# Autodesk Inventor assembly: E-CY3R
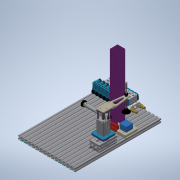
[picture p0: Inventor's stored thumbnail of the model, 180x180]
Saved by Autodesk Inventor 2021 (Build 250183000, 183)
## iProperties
Created: 2021-01
Part Number: E-CY3R
Material: Genérico
Document SubType Name: Assembly
Designer: ATOUZA
Author: ATOUZA
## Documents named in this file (20)
- D:\01 Paralaia\Grupos de Traballo\GT Maquetas\CAD 3D\E_AlimentaciónV1\EAV1.iam
- D:\01 Paralaia\Grupos de Traballo\GT Maquetas\CAD 3D\E_AlimentaciónV1\SMC_JP_MSQXB10AM9B0\MSQXB10A-M9B(0).iam
- D:\01 Paralaia\Grupos de Traballo\GT Maquetas\CAD 3D\E_AlimentaciónV1\SMC_JP_CDQMB2530M9B000\CDQMB25-30-M9B(0_0_0).iam
- D:\01 Paralaia\Grupos de Traballo\GT Maquetas\CAD 3D\E_AlimentaciónV1\Placa cilindro rotatorio.ipt
- D:\01 Paralaia\Grupos de Traballo\GT Maquetas\CAD 3D\E_AlimentaciónV1\Placa cilindro elevador.ipt
- D:\01 Paralaia\Grupos de Traballo\GT Maquetas\CAD 3D\E_AlimentaciónV1\SMC_JP_CD85N1650MBM9B000\CD85N16-50M-B-M9B(0__0_0).iam
- D:\01 Paralaia\Grupos de Traballo\GT Maquetas\CAD 3D\E_AlimentaciónV1\Cubo.ipt
- D:\01 Paralaia\Grupos de Traballo\GT Maquetas\CAD 3D\E_AlimentaciónV1\ZPT32SCK30\ZPT32CSK30-04-A10_(S) Silicon rubber.iam
- D:\01 Paralaia\Grupos de Traballo\GT Maquetas\CAD 3D\E_AlimentaciónV1\Alimentador.ipt
- D:\01 Paralaia\Grupos de Traballo\GT Maquetas\CAD 3D\E_AlimentaciónV1\LateralAlimentadorDcha.ipt
- D:\01 Paralaia\Grupos de Traballo\GT Maquetas\CAD 3D\E_AlimentaciónV1\EmpujadorCabeza.ipt
- D:\01 Paralaia\Grupos de Traballo\GT Maquetas\CAD 3D\E_AlimentaciónV1\EmpujadorHorizontal.ipt
- D:\01 Paralaia\Grupos de Traballo\GT Maquetas\CAD 3D\E_AlimentaciónV1\SoporteCilindro.ipt
- D:\01 Paralaia\Grupos de Traballo\GT Maquetas\CAD 3D\E_AlimentaciónV1\BrazoElevador.ipt
- D:\01 Paralaia\Grupos de Traballo\GT Maquetas\CAD 3D\E_AlimentaciónV1\BrazoVentosa.ipt
- D:\01 Paralaia\Grupos de Traballo\GT Maquetas\CAD 3D\E_AlimentaciónV1\Perfil 20x20 B R6.ipt
- D:\01 Paralaia\Grupos de Traballo\GT Maquetas\CAD 3D\E_AlimentaciónV1\LateralAlimentadorIzq.ipt
- D:\01 Paralaia\Grupos de Traballo\GT Maquetas\CAD 3D\E_AlimentaciónV1\PlacaDeslizaPieza.ipt
- D:\01 Paralaia\Grupos de Traballo\GT Maquetas\CAD 3D\E_AlimentaciónV1\TopePieza.ipt
- D:\01 Paralaia\Grupos de Traballo\GT Maquetas\CAD 3D\E_AlimentaciónV1\Electroválvulas\BloqueElectroválvulas.iam
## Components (34 placed, 19 different names)
1. MSQXB10A-M9B(0):1 [sub-assembly] — Coincidencia:7, Coincidencia:8, Coincidencia:9, Nivelación:10, Coincidencia:27, Nivelación:14, Ángulo:5
2. CDQMB25-30-M9B(0_0_0):1 [sub-assembly] — Nivelación:3, Insertar:1, Insertar:2, Insertar:9, Insertar:10
3. Placa cilindro rotatorio:1 — Coincidencia:4, Coincidencia:5, Coincidencia:6, Coincidencia:7, Coincidencia:8, Coincidencia:9, Ángulo:5
4. Placa cilindro elevador:1 — Nivelación:3, Coincidencia:4, Coincidencia:5, Coincidencia:6, Insertar:1, Insertar:2
5. CD85N16-50M-B-M9B(0__0_0):1 [sub-assembly] — Coincidencia:19, Insertar:5, Coincidencia:21, Insertar:6
6. Cubo:1 — Ángulo:3, Coincidencia:23, Coincidencia:24, Coincidencia:25, Ángulo:4, Nivelación:10, Coincidencia:27, Nivelación:12, Coincidencia:32
7. ZPT32CSK30-04-A10_(S) Silicon rubber:1 [sub-assembly] — Ángulo:4, Coincidencia:28, Nivelación:11
8. Alimentador:1 — Coincidencia:12, Coincidencia:17, Coincidencia:22, Coincidencia:23, Coincidencia:31, Nivelación:15
9. LateralAlimentadorDcha — Coincidencia:17, Coincidencia:29, Nivelación:12, Coincidencia:32, Insertar:12
10. LateralAlimentadorIzq:1 — Coincidencia:31, Nivelación:15, Insertar:11
11. EmpujadorCabeza:1 — Insertar:3, Insertar:4, Ángulo:1, Ángulo:2, Ángulo:3, Coincidencia:21, Insertar:6, Coincidencia:22, Coincidencia:24
12. EmpujadorHorizontal:1 — Insertar:3, Insertar:4, Coincidencia:19
13. SoporteCilindro:1 — Coincidencia:20, Insertar:5, Ángulo:1, Ángulo:2, Coincidencia:25
14. BrazoElevador:1 — Insertar:7, Insertar:8, Insertar:9, Insertar:10
15. BrazoVentosa:1 — Insertar:7, Insertar:8, Coincidencia:28, Nivelación:11
16. PlacaDeslizaPieza:1 — Nivelación:16, Nivelación:17, Coincidencia:33, Insertar:11, Insertar:12, Nivelación:18, Nivelación:19, Insertar:15, Insertar:16
17. TopePieza:1 — Nivelación:18, Nivelación:19, Insertar:13, Insertar:14, Insertar:15, Insertar:16
18. TopePieza:2 — Insertar:13, Insertar:14
19. BloqueElectroválvulas:1 [sub-assembly] — Coincidencia:34, Nivelación:20
20. Perfil 20x20 B R6 480:1 — Nivelación:13
21. Perfil 20x20 B R6 480:2 — Coincidencia:34
22. Perfil 20x20 B R6 480:3
23. Perfil 20x20 B R6 480:4 — Nivelación:20
24. Perfil 20x20 B R6 480:5
25. Perfil 20x20 B R6 480:6
26. Perfil 20x20 B R6 480:7
27. Perfil 20x20 B R6 480:8
28. Perfil 20x20 B R6 480:9
29. Perfil 20x20 B R6 480:10
30. Perfil 20x20 B R6 480:11
31. Perfil 20x20 B R6 480:12
32. Perfil 20x20 B R6 480:13
33. Perfil 20x20 B R6 480:14
34. Perfil 20x20 B R6 480:15 — Nivelación:14
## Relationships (55: Mate 22, Insert 16, Flush 12, Angle 5)
- Nivelación:3 [Flush]: CDQMB25-30-M9B(0_0_0):1 ↔ Placa cilindro elevador:1
- Coincidencia:4 [Mate]: Placa cilindro rotatorio:1 ↔ Placa cilindro elevador:1
- Coincidencia:5 [Mate]: Placa cilindro rotatorio:1 ↔ Placa cilindro elevador:1
- Coincidencia:6 [Mate]: Placa cilindro rotatorio:1 ↔ Placa cilindro elevador:1
- Coincidencia:7 [Mate]: MSQXB10A-M9B(0):1 ↔ Placa cilindro rotatorio:1
- Coincidencia:8 [Mate]: MSQXB10A-M9B(0):1 ↔ Placa cilindro rotatorio:1
- Coincidencia:9 [Mate]: MSQXB10A-M9B(0):1 ↔ Placa cilindro rotatorio:1
- Insertar:1: CDQMB25-30-M9B(0_0_0):1 ↔ Placa cilindro elevador:1
- Insertar:2: CDQMB25-30-M9B(0_0_0):1 ↔ Placa cilindro elevador:1
- Coincidencia:12 [Mate]: Alimentador:1
- Coincidencia:17 [Mate]: Alimentador:1 ↔ LateralAlimentadorDcha
- Insertar:3: EmpujadorCabeza:1 ↔ EmpujadorHorizontal:1
- Insertar:4: EmpujadorCabeza:1 ↔ EmpujadorHorizontal:1
- Coincidencia:19 [Mate]: CD85N16-50M-B-M9B(0__0_0):1 ↔ EmpujadorHorizontal:1
- Coincidencia:20 [Mate]: SoporteCilindro:1
- Insertar:5: CD85N16-50M-B-M9B(0__0_0):1 ↔ SoporteCilindro:1
- Ángulo:1 [Angle]: EmpujadorCabeza:1 ↔ SoporteCilindro:1
- Ángulo:2 [Angle]: EmpujadorCabeza:1 ↔ SoporteCilindro:1
- Ángulo:3 [Angle]: Cubo:1 ↔ EmpujadorCabeza:1
- Coincidencia:21 [Mate]: CD85N16-50M-B-M9B(0__0_0):1 ↔ EmpujadorCabeza:1
- Insertar:6: CD85N16-50M-B-M9B(0__0_0):1 ↔ EmpujadorCabeza:1
- Coincidencia:22 [Mate]: Alimentador:1 ↔ EmpujadorCabeza:1
- Coincidencia:23 [Mate]: Cubo:1 ↔ Alimentador:1
- Coincidencia:24 [Mate]: Cubo:1 ↔ EmpujadorCabeza:1
- Coincidencia:25 [Mate]: Cubo:1 ↔ SoporteCilindro:1
- Ángulo:4 [Angle]: Cubo:1 ↔ ZPT32CSK30-04-A10_(S) Silicon rubber:1
- Nivelación:10 [Flush]: MSQXB10A-M9B(0):1 ↔ Cubo:1
- Coincidencia:27 [Mate]: MSQXB10A-M9B(0):1 ↔ Cubo:1
- Insertar:7: BrazoElevador:1 ↔ BrazoVentosa:1
- Insertar:8: BrazoElevador:1 ↔ BrazoVentosa:1
- Insertar:9: CDQMB25-30-M9B(0_0_0):1 ↔ BrazoElevador:1
- Coincidencia:28 [Mate]: ZPT32CSK30-04-A10_(S) Silicon rubber:1 ↔ BrazoVentosa:1
- Insertar:10: CDQMB25-30-M9B(0_0_0):1 ↔ BrazoElevador:1
- Nivelación:11 [Flush]: ZPT32CSK30-04-A10_(S) Silicon rubber:1 ↔ BrazoVentosa:1
- Coincidencia:29 [Mate]: LateralAlimentadorDcha
- Nivelación:12 [Flush]: Cubo:1 ↔ LateralAlimentadorDcha
- Nivelación:13 [Flush]: Perfil 20x20 B R6 480:1
- Nivelación:14 [Flush]: MSQXB10A-M9B(0):1 ↔ Perfil 20x20 B R6 480:15
- Ángulo:5 [Angle]: MSQXB10A-M9B(0):1 ↔ Placa cilindro rotatorio:1
- Coincidencia:31 [Mate]: Alimentador:1 ↔ LateralAlimentadorIzq:1
- Nivelación:15 [Flush]: Alimentador:1 ↔ LateralAlimentadorIzq:1
- Coincidencia:32 [Mate]: Cubo:1 ↔ LateralAlimentadorDcha
- Nivelación:16 [Flush]: PlacaDeslizaPieza:1
- Nivelación:17 [Flush]: PlacaDeslizaPieza:1
- Coincidencia:33 [Mate]: PlacaDeslizaPieza:1
- Insertar:11: LateralAlimentadorIzq:1 ↔ PlacaDeslizaPieza:1
- Insertar:12: LateralAlimentadorDcha ↔ PlacaDeslizaPieza:1
- Nivelación:18 [Flush]: PlacaDeslizaPieza:1 ↔ TopePieza:1
- Nivelación:19 [Flush]: PlacaDeslizaPieza:1 ↔ TopePieza:1
- Insertar:13: TopePieza:1 ↔ TopePieza:2
- Insertar:14: TopePieza:1 ↔ TopePieza:2
- Insertar:15: PlacaDeslizaPieza:1 ↔ TopePieza:1
- Insertar:16: PlacaDeslizaPieza:1 ↔ TopePieza:1
- Coincidencia:34 [Mate]: BloqueElectroválvulas:1 ↔ Perfil 20x20 B R6 480:2
- Nivelación:20 [Flush]: BloqueElectroválvulas:1 ↔ Perfil 20x20 B R6 480:4
